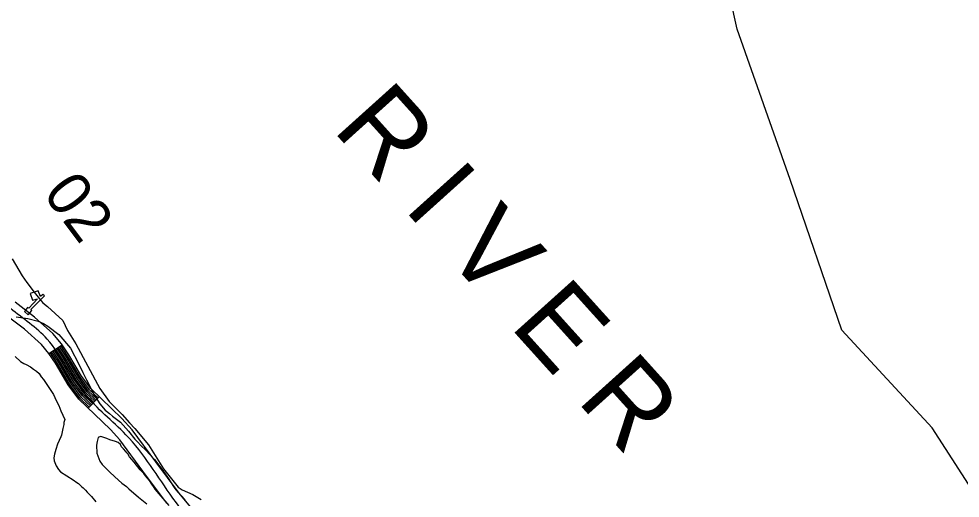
# Model space of a CAD drawing. Extents: x 3161564 to 3199464, y 849354 to 874788.
# Drawn here: x 3176490 to 3178273, y 856425 to 857334 of the extents above; entities that cross this region are included whole.
import ezdxf

# ---------------------------------------------------------------- set-up
doc = ezdxf.new("R2010")
doc.units = 0
for name, color, linetype in [('V-CHAN-DOCK', 7, 'Continuous'), ('V-RIVR-IDEN', 7, 'Continuous'), ('V-ROAD-CNTR', 7, 'Continuous'), ('V-SITE-VEGE', 7, 'Continuous'), ('V-TOPO-BNDY', 7, 'Continuous'), ('V-TOPO-SHOR', 7, 'Continuous'), ('V-WETL-SWMP', 7, 'Continuous')]:
    doc.layers.add(name, color=color, linetype=linetype)

msp = doc.modelspace()

# ---------------------------------------------------------------- linework, layer by layer
at = {"layer": 'V-CHAN-DOCK'}
msp.add_lwpolyline([(3176507.9, 856772.4), (3176514.8, 856780.8), (3176512.8, 856782.6), (3176539, 856808.8), (3176535.9, 856810.8), (3176531.5, 856807.1), (3176527.2, 856818), (3176511.7, 856813.2), (3176515.9, 856800.2), (3176525.4, 856802.9), (3176509, 856785.2), (3176506.9, 856786.4), (3176501.1, 856779.1), (3176507.9, 856772.4)], dxfattribs=at)
at = {"layer": 'V-ROAD-CNTR'}
for p, q in [((3176547.2, 856699.3), (3176572.2, 856715.8)), ((3176621.8, 856595.6), (3176642.5, 856617.2))]:
    msp.add_line(p, q, dxfattribs=at)
for points in [[(3176850, 856367), (3176794, 856434.4), (3176749.5, 856494), (3176704.8, 856554.8), (3176685.5, 856576.1), (3176626.5, 856632.6), (3176609, 856656.2), (3176584.9, 856696.6), (3176571.2, 856717.4), (3176554.7, 856737), (3176519.9, 856768.2), (3176483.3, 856796.3)], [(3176770.5, 856415.8), (3176725.4, 856476.1), (3176681.5, 856535.8), (3176664, 856555.1), (3176603.9, 856612.7), (3176584, 856639.5), (3176559.5, 856680.7), (3176547.1, 856699.4), (3176533.1, 856716), (3176500.7, 856745.1), (3176465.5, 856772.1)], [(3176623.8, 856597.7), (3176606.1, 856614.7), (3176586.5, 856641.2), (3176562, 856682.3), (3176549.7, 856700.9)], [(3176625.9, 856599.9), (3176608.4, 856616.7), (3176589, 856642.9), (3176564.6, 856683.9), (3176552.2, 856702.6)], [(3176628, 856602.1), (3176610.6, 856618.7), (3176591.5, 856644.5), (3176567.1, 856685.5), (3176554.7, 856704.2)], [(3176630.1, 856604.2), (3176612.9, 856620.7), (3176594, 856646.2), (3176569.6, 856687.1), (3176557.2, 856705.9)], [(3176632.1, 856606.4), (3176615.2, 856622.6), (3176596.5, 856647.8), (3176572.2, 856688.7), (3176559.7, 856707.5)], [(3176634.2, 856608.6), (3176617.4, 856624.6), (3176599, 856649.5), (3176574.7, 856690.2), (3176562.2, 856709.2)], [(3176636.3, 856610.7), (3176619.7, 856626.6), (3176601.5, 856651.2), (3176577.3, 856691.8), (3176564.7, 856710.8)], [(3176638.4, 856612.9), (3176621.9, 856628.6), (3176604, 856652.8), (3176579.8, 856693.4), (3176567.2, 856712.5)], [(3176640.4, 856615.1), (3176624.2, 856630.6), (3176606.5, 856654.5), (3176582.3, 856695), (3176569.7, 856714.2)]]:
    msp.add_lwpolyline(points, dxfattribs=at)
for points in [[(3176879.1, 855651.9), (3176902.3, 855659.1), (3176934.1, 855667), (3176983.4, 855657.7), (3177040.7, 855639.1), (3177110.5, 855613.6), (3177170.6, 855601.8), (3177236.8, 855586.9), (3177274.8, 855573.5), (3177317.4, 855579.8), (3177362.6, 855595.7), (3177412, 855643.1), (3177451.7, 855679.2), (3177476.7, 855705.8), (3177478.3, 855737), (3177464.2, 855782.3), (3177430.8, 855833.4), (3177373, 855887.8), (3177287.8, 855954.8), (3177219.8, 855998.4), (3177153, 856039.4), (3177089.3, 856079.2), (3177023.4, 856134.3), (3176966.6, 856207.9), (3176895.2, 856290.1), (3176782.2, 856425.1), (3176693.2, 856545.3), (3176615.2, 856622.6), (3176543.9, 856726.5), (3176474.4, 856784.2), (3176414.4, 856823.6), (3176395.9, 856828), (3176350.8, 856806.2), (3176279.1, 856754.7), (3176211.6, 856707.4), (3176172.3, 856696.1), (3176141.1, 856702), (3176111.7, 856719.6), (3176032.6, 856777.4), (3175933.6, 856857.4), (3175839, 856930.3), (3175807.1, 856951.5), (3175770.1, 856958.7), (3175787.1, 856991.4), (3175795.1, 857040.7), (3175799.5, 857113.7), (3175810.8, 857206.9), (3175813.7, 857287.4), (3175807.8, 857386.8), (3175805.7, 857497.9), (3175801.9, 857543.6), (3175783.5, 857620.5), (3175760.2, 857716.1), (3175755.3, 857765.5), (3175754.5, 857815.6), (3175751.7, 857884.3), (3175756.3, 858015.5), (3175754.9, 858158.6), (3175753.1, 858270.8), (3175748.6, 858321.7), (3175736.5, 858372), (3175677.2, 858555.5), (3175602.2, 858747.1), (3175558.2, 858866.9), (3175502.5, 858986.2), (3175436.3, 859092.6), (3175371.2, 859185.1), (3175300.7, 859261.6), (3175219.1, 859367.2), (3175166.2, 859443.7), (3175175.3, 859507.1), (3175222, 859537.9), (3175285.3, 859568.3), (3175321.2, 859607.5), (3175310.3, 859667.2), (3175262.4, 859798.6), (3175224.6, 859877.9), (3175174.7, 859982), (3175144.8, 860115.4), (3175122.6, 860284.8), (3175088.4, 860568.6), (3175086.3, 860704.5), (3175072.2, 860854.5), (3175052.5, 860999.9), (3175047.5, 861166.8), (3175053.2, 861343.7), (3175066.7, 861550.4), (3175065.5, 861662.5), (3175040.2, 861767.8), (3175017.8, 861884.2), (3175008.4, 862033.9), (3174979.6, 862160.3), (3174952.1, 862274.6), (3174921.6, 862422.8), (3174897, 862525.5), (3174861.7, 862663.2), (3174841.1, 862738)], [(3176024.8, 856482.2), (3176097.6, 856389.7), (3176177.6, 856292.7), (3176264, 856183.7), (3176352.4, 856075.4), (3176408.3, 856007.5), (3176463.7, 855948.5), (3176517.7, 855906.3), (3176602.7, 855849.1)]]:
    msp.add_spline(points, degree=3, dxfattribs=at)
at = {"layer": 'V-SITE-VEGE'}
for p, q in [((3176485.1, 856768.9), (3176507.1, 856765.3)), ((3176507.1, 856765.3), (3176527.2, 856760.5)), ((3176527.2, 856760.5), (3176536.7, 856756.2)), ((3176536.7, 856756.2), (3176545.5, 856751.2)), ((3176545.5, 856751.2), (3176566.3, 856735.1)), ((3176566.3, 856735.1), (3176587.9, 856709.5)), ((3176587.9, 856709.5), (3176603.8, 856678.9)), ((3176603.8, 856678.9), (3176611.5, 856663.3)), ((3176611.5, 856663.3), (3176618.5, 856649.5)), ((3176618.5, 856649.5), (3176633.1, 856620.8)), ((3176633.1, 856620.8), (3176644, 856603.9)), ((3176644, 856603.9), (3176654.1, 856592.1)), ((3176654.1, 856592.1), (3176656.6, 856590.2)), ((3176656.6, 856590.2), (3176661.7, 856585.2)), ((3176661.7, 856585.2), (3176668, 856580.3)), ((3176668, 856580.3), (3176683.1, 856569.1)), ((3176683.1, 856569.1), (3176697.7, 856552.3)), ((3176640.7, 856539.9), (3176638.9, 856532.3)), ((3176645.1, 856541.8), (3176640.7, 856539.9)), ((3176647.6, 856541.2), (3176645.1, 856541.8)), ((3176657, 856538.1), (3176647.6, 856541.2)), ((3176662.7, 856535.6), (3176657, 856538.1)), ((3176697.7, 856552.3), (3176709.8, 856536.7)), ((3176638.9, 856532.3), (3176637.7, 856525.4)), ((3176637.7, 856525.4), (3176637.8, 856510.3)), ((3176673.4, 856532.6), (3176662.7, 856535.6)), ((3176678.4, 856530.8), (3176673.4, 856532.6)), ((3176682.9, 856526.4), (3176678.4, 856530.8)), ((3176684.8, 856522.6), (3176682.9, 856526.4)), ((3176688.6, 856518.3), (3176684.8, 856522.6)), ((3176709.8, 856536.7), (3176714.8, 856531.7)), ((3176714.8, 856531.7), (3176721.8, 856524.2)), ((3176721.8, 856524.2), (3176730, 856516.7)), ((3176637.8, 856510.3), (3176643.6, 856495.3)), ((3176693, 856513.3), (3176688.6, 856518.3)), ((3176694.9, 856510.8), (3176693, 856513.3)), ((3176696.8, 856508.9), (3176694.9, 856510.8)), ((3176700, 856503.3), (3176696.8, 856508.9)), ((3176708.9, 856493.3), (3176700, 856503.3)), ((3176730, 856516.7), (3176747.1, 856498)), ((3176643.6, 856495.3), (3176648, 856489.1)), ((3176648, 856489.1), (3176656.3, 856480.4)), ((3176720.3, 856479), (3176708.9, 856493.3)), ((3176747.1, 856498), (3176749.6, 856494.9)), ((3176749.6, 856494.9), (3176758.5, 856483.1)), ((3176656.3, 856480.4), (3176661.9, 856474.8)), ((3176661.9, 856474.8), (3176672.1, 856465.4)), ((3176727.2, 856471.5), (3176720.3, 856479)), ((3176730.4, 856467.2), (3176727.2, 856471.5)), ((3176738, 856458.4), (3176730.4, 856467.2)), ((3176758.5, 856483.1), (3176763, 856477.5)), ((3176763, 856477.5), (3176773.1, 856463.1)), ((3176672.1, 856465.4), (3176685.3, 856453.6)), ((3176685.3, 856453.6), (3176694.2, 856447.4)), ((3176742.5, 856451.6), (3176738, 856458.4)), ((3176746.9, 856445.3), (3176742.5, 856451.6)), ((3176773.1, 856463.1), (3176783.3, 856446.9)), ((3176694.2, 856447.4), (3176698.6, 856442.4)), ((3176698.6, 856442.4), (3176716.9, 856426.9)), ((3176748.8, 856442.2), (3176746.9, 856445.3)), ((3176774.8, 856411), (3176748.8, 856442.2)), ((3176783.3, 856446.9), (3176785.8, 856443.1)), ((3176785.8, 856443.1), (3176791.5, 856436.3)), ((3176791.5, 856436.3), (3176797.9, 856430.1)), ((3176716.9, 856426.9), (3176732.7, 856414.5)), ((3176797.9, 856430.1), (3176805.5, 856422))]:
    msp.add_line(p, q, dxfattribs=at)
at = {"layer": 'V-TOPO-BNDY'}
for p, q in [((3177851.3, 857313.7), (3177802.6, 857527.1)), ((3177951.1, 857029.3), (3177851.3, 857313.7)), ((3178049.2, 856743.3), (3177951.1, 857029.3)), ((3178220.1, 856558.3), (3178049.2, 856743.3)), ((3178412, 856261), (3178220.1, 856558.3))]:
    msp.add_line(p, q, dxfattribs=at)
at = {"layer": 'V-TOPO-SHOR'}
msp.add_lwpolyline([(3176477.8, 856878.4), (3176496.7, 856846.2), (3176505.2, 856834), (3176519.6, 856815.7), (3176529.3, 856802.9), (3176535.6, 856795.5), (3176544.5, 856788.3), (3176573.9, 856761.5), (3176582.6, 856743), (3176598.1, 856717.3), (3176643.7, 856632.9), (3176661.3, 856607.9), (3176672.8, 856596.9), (3176685.8, 856583.7), (3176699.6, 856567.6), (3176709.8, 856557.2), (3176735.9, 856526.3), (3176764.6, 856480.8), (3176791.9, 856445.8), (3176799.9, 856440.7), (3176820, 856432.1), (3176835.5, 856422.6)], dxfattribs=at)
at = {"layer": 'V-WETL-SWMP'}
msp.add_lwpolyline([(3176483.4, 856693.8), (3176493.6, 856684), (3176496.5, 856682), (3176499.9, 856680.1), (3176504.4, 856678.1), (3176512.6, 856674), (3176518.3, 856669.8), (3176524, 856665.9), (3176528.8, 856661.1), (3176532.8, 856655.2), (3176537.1, 856649.6), (3176547, 856634.8), (3176556.2, 856621.6), (3176561.1, 856610.1), (3176565.9, 856600.8), (3176570, 856590.4), (3176577.4, 856574.1), (3176575.8, 856568.4), (3176575.3, 856564.5), (3176573.9, 856557.1), (3176571.2, 856544.7), (3176569.8, 856541), (3176566.5, 856534), (3176563.7, 856527.2), (3176560.1, 856517), (3176557.9, 856508.5), (3176556.6, 856501.2), (3176557.2, 856495.5), (3176560.9, 856486.2), (3176565.2, 856479.2), (3176569.2, 856474.7), (3176593.3, 856460), (3176600.1, 856454.4), (3176603, 856452.5), (3176609.8, 856446.6), (3176612.3, 856444.6), (3176616.6, 856440.4), (3176620, 856436.5), (3176627.7, 856428.4), (3176636, 856417.8)], dxfattribs=at)

# ---------------------------------------------------------------- texts
at = {"layer": 'V-RIVR-IDEN'}
for s, height, rotation, p in [('R I V E R', 150, 312.0166, (3177082.6, 857123.6)), ('02', 83, 306.861, (3176534.1, 857002.2))]:
    msp.add_text(s, height=height, rotation=rotation, dxfattribs=at).set_placement(p)

doc.saveas('drawing.dxf')
